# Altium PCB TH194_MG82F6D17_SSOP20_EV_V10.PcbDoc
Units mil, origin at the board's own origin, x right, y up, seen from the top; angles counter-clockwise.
Board outline 2850 x 2110 mil, 2 copper layers (Top Layer, Bottom Layer); 42 components, 34 nets, 215 pads, 149 vias.
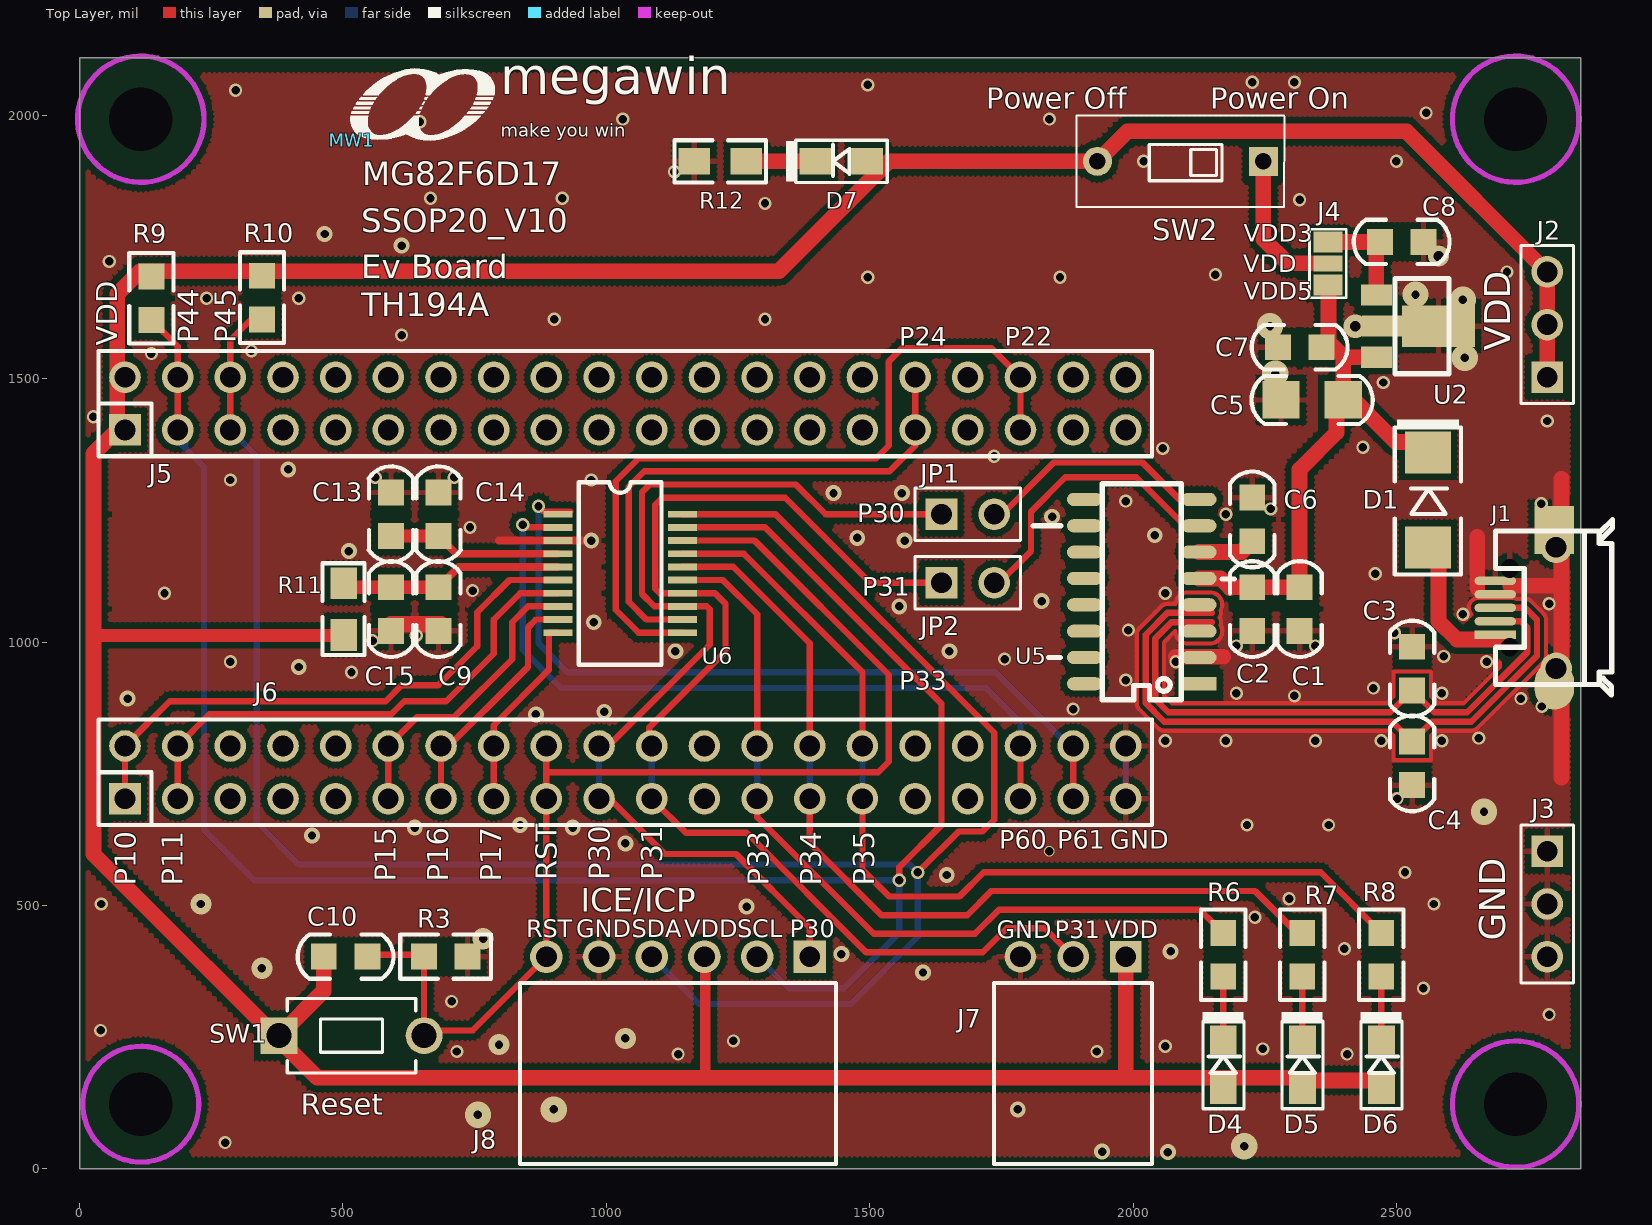
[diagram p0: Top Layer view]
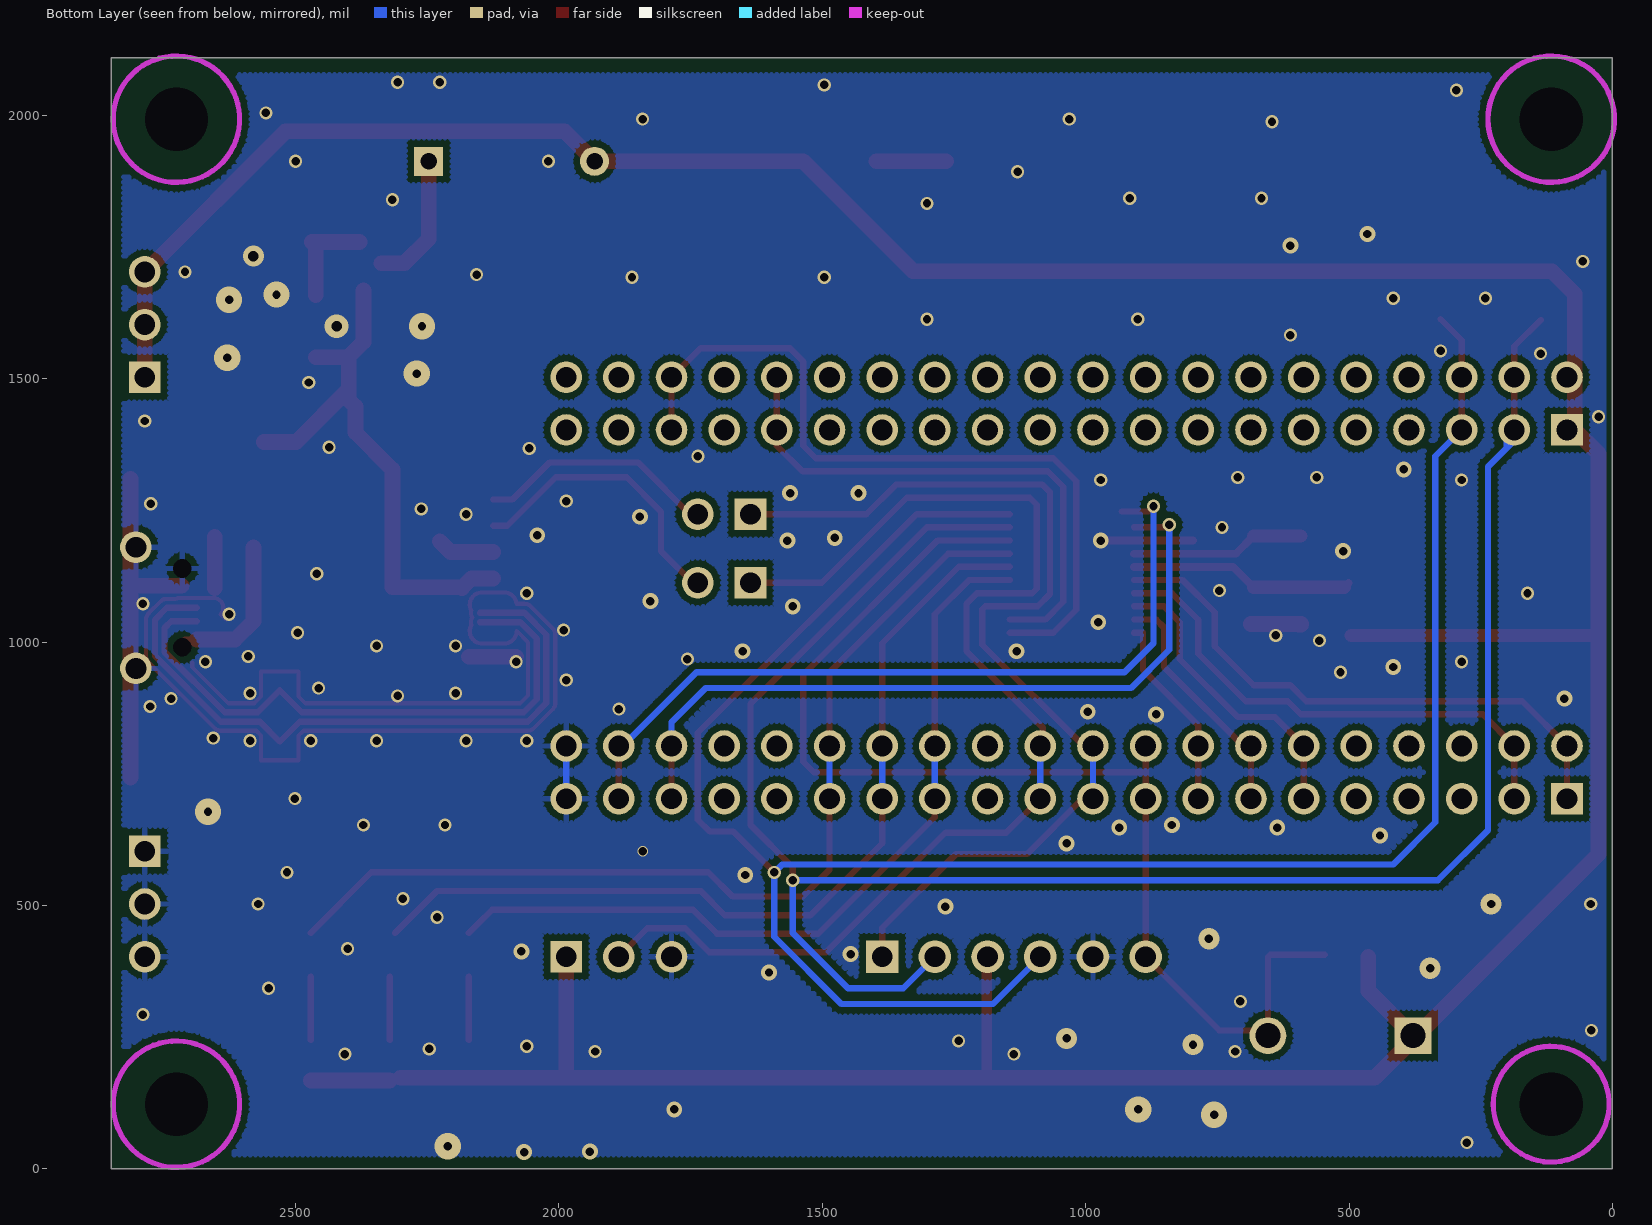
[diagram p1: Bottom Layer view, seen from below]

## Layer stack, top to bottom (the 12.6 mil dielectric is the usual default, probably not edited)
Top Layer: signal copper 1.4
Dielectric: dielectric 12.6, FR-4, Dk 4.8
Bottom Layer: signal copper 1.4

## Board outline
0,0 2850,0 2850,2110 0,2110

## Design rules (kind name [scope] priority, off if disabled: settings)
Clearance 12 [All] p1 off: gap=12
Clearance 7 [All] p2 off: gap=7
Clearance 6 [All] p3: gap=6
ComponentClearance [All] p1 off: gap=10 collisioncheckmode=3 verticalgap=10 showdistances=FALSE
HoleSize [All] p1: absolutevalues=TRUE maxlimit=500 minlimit=1 maxpercent=80.000 minpercent=20.000
MinimumSolderMaskSliver [All] p1 off: minsoldermaskwidth=10
PolygonConnect VIA [ISVIA] p1: connectstyle=Direct reliefconductorwidth=10 reliefentries=4 polygonreliefangle="90 Angle"
PolygonConnect [All] p2: connectstyle=Relief reliefconductorwidth=10 reliefentries=4 polygonreliefangle="90 Angle"
RoutingVias [All] p1: holewidth=16 width=25 viastyle="Through Hole" minholewidth=16 minwidth=24 maxholewidth=28 maxwidth=50
SilkToSilkClearance [All] p1 off: silktosilkclearance=10
SilkscreenOverComponentPads [All] p1 off: minsilkscreentomaskgap=10
SolderMaskExpansion [All] p1 off: expansion=4
Width [All] p1: maxlimit=200 minlimit=6 preferedwidth=10
23 further rules are at their usual default settings.

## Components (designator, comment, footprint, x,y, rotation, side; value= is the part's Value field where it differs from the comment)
C1 "4.7uF" 0805C 2316.34,1063 r270 top
C2 "0.1uF" 0805C 2226.34,1063 r90 top
C3 "15pF" 0805C 2530,950 r90 top
C4 "15pF" 0805C 2530,770 r270 top
C5 "4.7uF" 1206C 2340,1460 r180 top
C6 "1uF" 0805C 2226.34,1233 r270 top
C7 "0.1uF" 0805C 2316.34,1560 r180 top
C8 "4.7uF" 0805C 2510,1760 r0 top
C9 "0.1uF" 0805C 681.34,1063 r90 top
C10 "4.7uF" 0805C 505,403 r0 top
C13 "4.7uF" 0805C 591.34,1243 r90 top
C14 "0.1uF" 0805C 681.34,1243 r270 top
C15 "4.7uF" 0805C 591.34,1063 r270 top
D1 "1N5817" D5817_SMD_1 2560,1270 r270 top
D4 "Green" 0805D#1 2171.34,198 r90 top
D5 "Red" 0805D#1 2321.34,198 r90 top
D6 "Green" 0805D#1 2471.34,198 r90 top
D7 "Yellow" 0805D#2 1446.34,1913 r180 top
J1 "Micro USB母座" JACK_USB_SMD290X220P065 2687.8,1065.28 r180 top
J2 "CON3" PS3P254 2786.34,1503 r90 top
J3 "CON3" PS3P254 2786.34,603 r270 top
J4 "*" JUMP3_SMD 2370,1719 r90 top
J5 "CON40A" PS20X2P254 86.34,1403 r0 top locked
J6 "CON40A" PS20X2P254 86.34,703 r0 top locked
J7 "*" PS3P254f_90 1986.34,403 r180 top
J8 "*" PS6P254F_90 1386.34,403 r180 top locked
JP1 "JUMPER2" PS2P254 1636.34,1243 r0 top
JP2 "JUMPER2" PS2P254 1636.34,1113 r0 top
MW1 "MW-A4" MEGAWIN_3.4 516.34,1953 r0 top
R3 "47K" 0805R#1 695,403 r180 top
R6 "1K" 0805R#1 2171.34,406.66 r270 top
R7 "1K" 0805R#1 2321.34,406.66 r270 top
R8 "1K" 0805R#1 2471.34,406.66 r270 top
R9 "4.7K" 0805R#1 136.34,1653 r90 top
R10 "4.7K" 0805R#1 346.34,1654.34 r90 top
R11 "10" 0805R#2 501.34,1063 r90 top
R12 "1K" 0805R#2 1216.34,1913 r0 top
SW1 "SW TACT-SPST" SW_T_2P 516.34,253 r0 top
SW2 "指撥開關" DIP2_SW 2247.38,1913 r180 top
U2 "AIC1734-33(SOT-89)" SOT89 2461.89,1600 r270 top
U5 "MA111AS16" SO16_150P127 2016.5,1096 r180 top
U6 "MG82F6D17_SSOP-20(150mil)" SSOP20_150P0635 1026.34,1130.5 r270 top

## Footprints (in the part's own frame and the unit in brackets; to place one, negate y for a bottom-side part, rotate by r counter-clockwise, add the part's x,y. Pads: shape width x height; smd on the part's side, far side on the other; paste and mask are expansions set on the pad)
0805C [mm]
  rect 1.25x1.25 smd: 1(-1.05,0) 2(1.05,0)
  silkscreen extent -2.31,-1.07 2.31,1.07
0805D#1 [mm]
  rect 1.4x1.3 smd: 1(-1.192,0) 2(1.192,0)
  silkscreen extent -2.12,-1 2.53,1
0805D#2 [mm]
  rect 1.524x1.27 smd: 1(-1.25,0) 2(1.25,0)
  silkscreen extent -2.21,-1.02 2.67,1.02
0805R#1 [mm]
  rect 1.25x1.25 smd: 1(-1.05,0) 2(1.05,0)
  silkscreen extent -2.18,-1.07 2.18,1.07
0805R#2 [mm]
  rect 1.524x1.27 smd: 1(-1.25,0) 2(1.25,0)
  silkscreen extent -2.21,-1.02 2.21,1.02
1206C [mm]
  rect 1.8x1.8 smd: 1(-1.5,0) 2(1.5,0)
  silkscreen extent -2.92,-1.15 2.92,1.16
D5817_SMD_1 [mil]
  rect 80x86.61 smd: 1(90,0) 2(-90,0)
  silkscreen extent -153,-63 142,63
DIP2_SW [mm]
  rect 1.4x1.4 hole 0.8: 1(0,0)
  round 1.4 hole 0.8: 2(8,0)
  silkscreen extent -1.02,-2.2 9.02,2.2
JACK_USB_SMD290X220P065 [mm]
  rect 1.9x1.8 on Mech2: 0(-2.85,-1.15) 0(-2.85,1.15)
  round 0.8 hole 0.9 unplated: 1(-0.7,1.9) 5(-0.7,-1.9)
  rect 2x0.4 smd: 1(0,1.3)
  oval 2x0.4 smd: 2(0,0.65) 3(0,0) 4(0,-0.65) 5(0,-1.3)
  round 1.524 hole 1: 5(-2.931,2.921) 5(-2.931,-2.921)
  oval 1.9x2.3 smd: 5(-2.85,3.75)
  rect 1.9x2.3 smd: 5(-2.85,-3.75)
  silkscreen extent -5.65,-4.25 -0.01,4.2
JUMP3_SMD [mil]
  rect 40x55 smd: 1(-41,0) 3(41,0)
  rect 30x55 smd: 2(0,0)
  silkscreen extent -65,-35 65,35
MEGAWIN_3.4 [mil]
  silkscreen extent -2,0 272,135
PS2P254 [mil]
  rect 60x60 hole 39.37: 1(0,0)
  round 60 hole 39.37: 2(100,0)
  silkscreen extent -50,-50 150,50
PS3P254 [mil]
  rect 60x60 hole 39.37: 1(0,0)
  round 60 hole 39.37: 2(100,0) 3(200,0)
  silkscreen extent -50,-50 250,50
PS3P254f_90 [mil]
  rect 60x60 hole 39.37: 1(0,0)
  round 60 hole 39.37: 2(100,0) 3(200,0)
  silkscreen extent -50,50 250,394
PS6P254F_90 [mil]
  rect 62x62 hole 39.37: 1(0,0)
  round 62 hole 39.37: 2(100,0) 3(200,0) 4(300,0) 5(400,0) 6(500,0)
  silkscreen extent -50,50 550,394
PS20X2P254 [mil]
  rect 60x60 hole 39.37: 1(0,0)
  round 60 hole 39.37: 2(0,100) 3(100,0) 4(100,100) 5(200,0) 6(200,100) 7(300,0) 8(300,100) 9(400,0) 10(400,100) 11(500,0) 12(500,100) 13(600,0) 14(600,100) 15(700,0) 16(700,100) 17(800,0) 18(800,100) 19(900,0) 20(900,100) 21(1000,0) 22(1000,100) 23(1100,0) 24(1100,100) 25(1200,0) 26(1200,100) 27(1300,0) 28(1300,100) 29(1400,0) 30(1400,100) 31(1500,0) 32(1500,100) 33(1600,0) 34(1600,100) 35(1700,0) 36(1700,100) 37(1800,0) 38(1800,100) 39(1900,0) 40(1900,100)
  silkscreen extent -50,-50 1950,150
SO16_150P127 [mil]
  rect 67x25 smd: 1(-108.5,175)
  oval 67x25 smd: 2(-108.5,125) 3(-108.5,75) 4(-108.5,25) 5(-108.5,-25) 6(-108.5,-75) 7(-108.5,-125) 8(-108.5,-175) 9(108.5,-175) 10(108.5,-125) 11(108.5,-75) 12(108.5,-25) 13(108.5,25) 14(108.5,75) 15(108.5,125) 16(108.5,175)
  silkscreen extent -176,-205 206,205
SOT89 [mm]
  rect 1.016x1.5 smd: 1(-1.5,0) 3(1.5,0)
  rect 2x3.5 smd: 2(0,3)
  rect 1.016x2.6 smd: 2(0,0.6)
  silkscreen extent -2.3,0.9 2.3,3.5
SSOP20_150P0635 [mil]
  rect 13x55.12 smd: 1(-112.5,-118.11) 2(-87.5,-118.11) 3(-62.5,-118.11) 4(-37.5,-118.11) 5(-12.5,-118.11) 7(37.5,-118.11) 8(62.5,-118.11) 9(87.5,-118.11) 10(112.5,-118.11) 11(112.5,118.11) 12(87.5,118.11) 13(62.5,118.11) 14(37.5,118.11) 15(12.5,118.11) 16(-12.5,118.11) 17(-37.5,118.11) 18(-62.5,118.11) 19(-87.5,118.11) 20(-112.5,118.11)
  rect 13x55.12 smd mask+4: 6(12.5,-118.11)
  silkscreen extent -173,-79 173,79
SW_T_2P [mil]
  rect 70x70 hole 47.24: 1(-137.79,0)
  round 70 hole 47.24: 2(137.79,0)
  silkscreen extent -122,-71 122,71

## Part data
C1 C5 C8 C13 C15: library part CAP
C2 C3 C4 C6 C7 C9 C14: library part "CAP NP"
C10: library part C
D1: library part DIODE_ZD, "Schottky Diode"
D4 D5 D6 D7: library part LED
J1: library part CON5, "Connector"
J4 J7: library part CON3
J8: library part CON6
R3 R9 R10 R11: library part R
R6 R7 R8 R12: library part R_Dup1
SW2: library part SW-2
U2: library part AIC1734-33(SOT-89)_0
U6: library part MG82G6D17_SSOP-20

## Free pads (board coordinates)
  round 40 hole 120 unplated: 0(116.34,123) 0(116.34,1993) 0(2726.34,123) 0(2726.34,1993)

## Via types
v1: diameter 25, hole 16, Top Layer to Bottom Layer, tented both sides, 99 vias
v2: diameter 30, hole 16, Top Layer to Bottom Layer, tented both sides, 33 vias
v3: diameter 50, hole 16, Top Layer to Bottom Layer, tented both sides, 9 vias
v4: diameter 40, hole 16, Top Layer to Bottom Layer, tented both sides, 5 vias
v5: diameter 45, hole 20, Top Layer to Bottom Layer, tented both sides, 1 vias
v6: diameter 40, hole 20, Top Layer to Bottom Layer, tented both sides, 1 vias
v7: diameter 20, hole 16, Top Layer to Bottom Layer, tented both sides, 1 vias

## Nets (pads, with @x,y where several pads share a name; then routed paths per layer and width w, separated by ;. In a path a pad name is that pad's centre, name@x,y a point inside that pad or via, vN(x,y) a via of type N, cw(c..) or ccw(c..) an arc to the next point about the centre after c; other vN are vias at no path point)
D+: C4.1 J1.3 U5.4 | length 1271.3
  Top Layer w12: 2150,1056 2065.54,1056 2024,1014.46 2024,884.54 2059.54,849 2492.34,849 C4.1 2567.66,849 2642,849 2767,974 2767,1043 2744.72,1065.28 J1.3
D-: C3.1 J1.2 U5.3 | length 1147.1
  Top Layer w12: 2150,1038 2073,1038 2042,1007 2042,892 2067,867 2488.34,867 C3.1 2571.66,867 2634.54,867 2749,981.46 2749,1027 2736.32,1039.69 J1.2
GND_POWER: C1.2 C2.1 C3.2 C4.2 C5.2 C6.1 C7.2 C8.2 C9.1 C13.2 C14.1 C15.2 J1.4 J1.5 J3.1 J3.2 J3.3 J6.39 J6.40 J7.3 J8.5 R3.1 R12.1 U2.2 U5.2 U6.3 | length 4084.9
  Top Layer w8: 2047.52,836.98 ccw(c2059.54,849) 2059.54,832 ; 2053.52,1068.02 cw(c2065.54,1056) 2065.54,1073 ; 2080.04,1021 2059,999.96 2059,899.04 2074.04,884 2481.3,884 2494.39,897.1 2494.39,944.27 2565.61,944.27 2565.61,897.1 2578.7,884 2627.5,884 2696.4,952.9 2696.4,961.39 ; 2080.5,1021 ccw(c2104,1021) 2104,997.5 2146,997.5 ccw(c2146,1021) 2169.5,1021 ccw(c2146,1021) 2166.23,1032.95 ccw(c2150,1038) 2167,1038 ccw(c2150,1038) 2164.42,1047 ccw(c2150,1056) 2167,1056 ccw(c2150,1056) 2166.6,1059.68 ccw(c2146,1071) 2169.5,1071 ccw(c2146,1071) 2146,1094.5 2104,1094.5 ccw(c2104,1071) 2080.59,1073 2065.54,1073 ; v1@2626.34,1055 2633.62,1055 2633.11,1051.88 2631.65,1043 2633.61,1044.73 2642.42,1052.48 cw(c2656.3,1065.28) 2656.3,1084.15 2719.29,1084.15 cw(c2719.29,1065.28) 2727.49,1082.28 2744.72,1082.28 ; 2756.75,1077.3 ccw(c2744.72,1065.28) 2744.72,1082.28 ; J1.5@2779.02,961.98 ccw(c2767,974) 2784,974 ; 2779.02,1055.02 cw(c2767,1043) 2784,1043 ; 2007,884.54 ccw(c2024,884.54) 2011.98,872.52 ; 2007,884.54 ccw(c2024,884.54) 2012,872.5 ; 2007,884.54 2007,1014.46 ; 2007,1014.46 cw(c2024,1014.46) 2012,1026.5 ; 2007,1014.46 cw(c2024,1014.46) 2011.98,1026.48 ; 2012,872.5 2047.5,837 ccw(c2059.54,849) 2059.54,832 ; 2012,1026.5 2053.5,1068 cw(c2065.54,1056) 2065.54,1073 ; 2059.54,832 2485.3,832 2494.39,822.9 2494.39,775.73 2565.61,775.73 2565.61,822.9 2574.7,832 2642,832 ; 2642,832 ccw(c2642,849) 2654.02,836.98 ; 2642,832 ccw(c2642,849) 2654.04,837 ; 2654.04,837 2779,961.96 ccw(c2767,974) 2784,974 ; 2744.72,1082.28 cw(c2744.72,1065.28) 2756.76,1077.28 2779,1055.04 cw(c2767,1043) 2784,1043 ; 2784,974 2784,1043
  Top Layer w12: U6.3@911.34,1193 v2(971.34,1193) v2@976.34,1193
  Top Layer w15: 796.34,1193 U6.3 v2(971.34,1193)
  Top Layer w30: C15.2@591.34,1033 C15.2@596.34,1033 ; C15.2@591.34,1034.34 681.34,1034.34 C9.1@686.34,1034.34 ; v1@2081.34,972.34 2171.34,972.34 ; 2653.66,1102.91 2653.66,1200 ; 2716.34,1107.32 2813.43,1107.32 ; 2813.66,743 2813.66,1310
  Bottom Layer w12: J6.39 J6.40
  other v1: 276.34,50 1136.34,218 2406.34,218 716.34,223 1931.34,223 2246.34,228 2061.34,233 1241.34,243 40,263 2790,293 706.34,318 2551.34,343 2401.34,418 2231.34,478 41.34,503 2571.34,503 2296.34,513 2516.34,563 2216.34,653 2371.34,653 2501.34,703 2061.34,813 2176.34,813 2346.34,813 2471.34,813 2586.34,813 2656.34,818 1886.34,873 2776.34,878 2736.34,893 2306.34,898 2196.34,903 2586.34,903 2456.34,913 1986.34,928 516.34,943 286.34,963 2081.34,963 2671.34,963 1756.34,968 2590,973 2196.34,993 2346.34,993 556.34,1003 639.34,1013 2496.34,1018 1991.34,1023 2626.34,1053 2790,1073 161.34,1093 2061.34,1093 746.34,1098 2460,1130 741.34,1218 2176.34,1243 2261.34,1253 2775,1263 1986.34,1268 286.34,1308 971.34,1308 561.34,1313 711.34,1313 1736.34,1353 2056.34,1368 2436.34,1370 2786.34,1420 26.34,1428 2475,1493 136.34,1548 326.34,1553 611.34,1583 901.34,1613 1301.34,1613 241.34,1653 416.34,1653 1496.34,1693 1861.34,1693 2156.34,1698 2710,1703 56.34,1723 1301.34,1833 2316.34,1840 666.34,1843 916.34,1843 1129.34,1893 2020,1913 2500,1913 646.34,1988 1031.34,1993 1841.34,1993 2556.34,2005 296.34,2048 1496.34,2058 2226.34,2063 2306.34,2063
  other v2: 2066.34,32 1941.34,33 1781.34,113 1601.34,373 1446.34,408 2071.34,413 1266.34,498 1646.34,558 1036.34,618 441.34,633 636.34,648 936.34,648 836.34,653 866.34,863 996.34,868 91.34,893 416.34,953 1131.34,983 1651.34,983 976.34,1038 1556.34,1068 1826.34,1078 511.34,1173 1566.34,1193 1476.34,1198 2041.34,1203 1846.34,1238 1431.34,1283 1561.34,1283 396.34,1328 611.34,1753 465.34,1775
  other v3: 2211.34,43 756.34,103 900.34,113 2666.34,678 2270,1510 2630,1540 2260,1600 2626.34,1650 2536.34,1660
  other v4: 796.34,236 1036.34,248 346.34,381 766.34,437 230.34,503
  other v5: 2422.33,1600
  other v6: 2580,1733
  other v7: 1841.34,603
MA111_RX: JP2.2 U5.7 | length 550.6
  Top Layer w12: JP2.2@1741.34,1108 1806.34,1173 1806.34,1248 1871.34,1313 2006.34,1313 2098.34,1221 U5.7
MA111_TX: JP1.2 U5.8 | length 454.1
  Top Layer w12: JP1.2@1743.84,1235.5 1849.62,1341.28 2018.05,1341.28 2088.34,1271 U5.8
NetC6_2: C6.2 U5.6 | length 109.9
  Top Layer w30: U5.6 2205.68,1171 C6.2
NetC9_2: C9.2 C15.1 R11.2 U6.5 | length 426.2
  Top Layer w15: R11.2 R11.2@509.21,1104.34 ; C9.2 720,1143 U6.5
  Top Layer w25: R11.2@509.21,1104.34 C15.1 C9.2
NetC13_1: C13.1 C14.2 U6.4 | length 330.8
  Top Layer w15: C14.2 715,1168 U6.4
  Top Layer w25: C13.1 C14.2
NetD1_1: D1.1 J1.1 | length 284.5
  Top Layer w12: 2687.8,1005 J1.1@2710,1005
  Top Layer w30: D1.1@2580,1180 2580,1040 2615,1005 2687.8,1005
NetD4_2: D4.2 R6.2 | length 120.4
  Top Layer w12: D4.2 R6.2
NetD5_2: D5.2 R7.2 | length 120.4
  Top Layer w12: D5.2 R7.2
NetD6_2: D6.2 R8.2 | length 120.4
  Top Layer w12: D6.2 R8.2
NetD7_2: D7.2 R12.2 | length 131.6
  Top Layer w30: R12.2 D7.2
NetJ4_2: J4.2 SW2.1 | length 256.1
  Top Layer w30: SW2.1 2247.38,1765.62 2293.5,1719.5 2337,1719.5
P10: J6.1 J6.2 U6.6 | length 1090.4
  Top Layer w12: J6.1 J6.2 171.34,888 581.34,888 611.34,918 681.34,918 755.34,992 755.34,1057 816.34,1118 U6.6
P11: J6.3 J6.4 U6.7 | length 980.1
  Top Layer w12: J6.3 J6.4 246.34,863 591.69,863 616.69,888 696.34,888 786.34,978 786.34,1043 836.34,1093 U6.7
P15: J6.11 J6.12 U6.8 | length 572.7
  Top Layer w12: J6.11 J6.12 641.34,858 711.34,858 821.34,968 821.34,1038 851.34,1068 U6.8
P16: J6.13 J6.14 U6.9 | length 456.4
  Top Layer w12: J6.13 686.34,788 851.34,953 851.34,1028 866.34,1043 U6.9
P17: J6.15 J6.16 U6.10 | length 375.4
  Top Layer w12: J6.15 J6.16 786.34,842.64 891.34,947.64 891.34,1018 U6.10
P22: J5.35 J5.36 U6.11 | length 1495
  Top Layer w12: U6.11 1061.34,1018 1017.76,1061.58 1017.76,1305.48 1061.69,1349.42 1151.34,1349.42 ; 1168.05,1349.42 1151.34,1349.42 ; J5.35 J5.36 1731.34,1558 1561.34,1558 1536.34,1533 1536.34,1373 1512.76,1349.42 1151.34,1349.42
P24: J5.31 J5.32 U6.12 | length 1147.4
  Top Layer w12: U6.12 1076.34,1043 1042.76,1076.58 1042.76,1295.13 1072.05,1324.42 ; 1168.05,1324.42 1072.05,1324.42 ; 1372.76,1324.42 1361.34,1324.42 ; J5.32 J5.31 1586.34,1373 1537.76,1324.42 1361.34,1324.42 ; 1072.05,1324.42 1361.34,1324.42
P30/RXD: J6.19 J6.20 J8.1 JP1.1 U6.13 | length 2013.8
  Top Layer w12: J6.19 1006.34,703 1111.34,598 1246.34,598 1386.34,458 J8.1 ; J6.20 1003.91,803 1196.34,995.43 1196.34,1062.64 1190.98,1068 U6.13 1091.34,1068 1067.76,1091.58 1067.76,1284.77 1082.4,1299.42 1236.34,1299.42 ; 1304.92,1299.42 1236.34,1299.42 ; JP1.1 1416.34,1243 1359.92,1299.42 1236.34,1299.42
  Bottom Layer w12: J6.19 J6.20
P31/TXD: J6.21 J6.22 J7.2 JP2.1 U6.14 | length 2325.1
  Top Layer w12: J6.22@1081.34,808 1081.34,838 1226.34,983 1226.34,1073 1206.34,1093 U6.14 1101.34,1093 1092.76,1101.58 1092.76,1260.83 1106.34,1274.42 1271.34,1274.42 ; J6.21 1151.34,638 1266.34,638 1493.16,411.17 1714.51,411.17 1760.27,456.93 1832.4,456.93 J7.2 ; 1288.5,1274.42 1271.34,1274.42 ; JP2.1 1501.34,1113 1339.92,1274.42 1271.34,1274.42
  Bottom Layer w12: J6.21 J6.22
P33: J6.25 J6.26 R6.1 U6.15 | length 1628.7
  Top Layer w12: U6.15 1221.34,1118 1286.34,1053 J6.26 ; J6.25 1286.34,668 1507.81,446.53 1699.87,446.53 1745.63,492.29 1801.34,492.29 ; 1821.34,492.29 1801.34,492.29 ; 2142.45,476.89 R6.1 2127.05,492.29 1801.34,492.29
  Bottom Layer w12: J6.25 J6.26
P34: J6.27 J6.28 R7.1 U6.16 | length 1866.8
  Top Layer w12: U6.16 1241.34,1143 ; 1311.34,1073 1241.34,1143 ; J6.27 1386.34,618 1522.45,481.89 1685.22,481.89 1730.98,527.64 1796.34,527.64 ; J6.28 1386.34,998 1241.34,1143 ; 1821.34,527.64 1796.34,527.64 ; 2248.16,511.18 2267.66,491.68 ; R7.1@2311.34,448 2267.66,491.68 ; 1796.34,527.64 2231.69,527.64 2267.66,491.68
  Bottom Layer w12: J6.27 J6.28
P35: J6.29 J6.30 R8.1 U6.17 | length 1998.8
  Top Layer w12: U6.17 1261.34,1168 ; 1336.34,1093 1261.34,1168 ; J6.29 1486.34,568 1537.1,517.24 1670.58,517.24 1716.34,563 1811.34,563 ; J6.30 1486.34,943 1261.34,1168 ; 1821.34,563 1811.34,563 ; R8.1 2356.34,563 1811.34,563
  Bottom Layer w12: J6.29 J6.30
P44: J5.3 J5.4 J8.2 R9.1 U6.19 | length 3941.2
  Top Layer w12: R9.1 186.34,1561.66 J5.4 J5.3 ; U6.19 1301.34,1218 1636.34,883 1636.34,653 1556.34,573 v1(1556.34,548)
  Bottom Layer w12: J5.3@186.34,1383 236.34,1333 236.34,643 ; 201.34,1373 J5.3@201.34,1393 ; 281.34,598 236.34,643 ; 971.34,548 1021.34,548 ; J8.2 1346.34,343 1451.34,343 1556.34,448 v1(1556.34,548) 1021.34,548 ; J8.2@1288.34,405 J8.2@1288.34,426 ; 236.34,643 331.34,548 1021.34,548
P45: J5.5 J5.6 J8.4 R10.1 U6.20 | length 4801.1
  Top Layer w12: J5.5 J5.6 286.34,1573 R10.1@326.34,1613 ; 1276.34,1243 U6.20 1321.34,1243 1736.34,828 1736.34,663 1713.89,640.55 1668.89,640.55 v1(1591.34,563)
  Bottom Layer w12: J5.5 336.34,1353 336.34,658 416.34,578 1516.34,578 ; 1001.34,578 1516.34,578 ; J8.4@1077.84,415.5 1088.34,426 J8.4@1088.34,406 ; J8.4 1176.34,313 1463.77,313 1591.34,440.57 v1(1591.34,563) 1576.34,578 1516.34,578
P60: J6.35 J6.36 U6.2 | length 1446.3
  Top Layer w12: v1@841.34,1218 U6.2 ; J6.35 J6.36
  Bottom Layer w12: v1@841.34,1218 841.34,985.57 913.91,913 1721.34,913 1786.34,848 J6.36
  other v1: 841.34,1223
P61: J6.37 J6.38 U6.1 | length 1512.4
  Top Layer w12: v1(871.34,1258) 881.34,1248 U6.1@931.34,1248 ; J6.37 J6.38
  Bottom Layer w12: v1(871.34,1258) 871.34,998 926.34,943 1738.87,943 J6.38@1878.87,803
RST: C10.2 J6.17 J6.18 J8.6 R3.2 SW1.2 U6.18 | length 2271
  Top Layer w12: C10.2@546.34,406.81 R3.2@649.85,406.81 ; R3.2@654.13,402.53 654.13,263 746.34,263 J8.6 ; J8.6@886.34,407 J6.17 886.34,753 ; J6.18 886.34,753 ; J8.6@888.34,405 J8.6@888.34,426 ; U6.18 1281.34,1193 1536.34,938 1536.34,773 1516.34,753 886.34,753
VDD: C10.1 D4.1 D5.1 D6.1 D7.1 J2.1 J2.2 J2.3 J5.1 J5.2 J7.1 J8.3 R9.2 R10.2 R11.1 SW1.1 SW2.2 | length 7958.3
  Top Layer w20: 1188.34,180 J8.3@1188.34,403
  Top Layer w25: 26.34,1013 R11.1@496.34,1013
  Top Layer w30: SW1.1 463.66,338.12 C10.1 ; SW1.1@382.74,249.56 SW1.1@382.82,252.9 ; J7.1@1986.34,413 J7.1 1986.34,173 ; D5.1@2301.34,173 1986.34,173 ; D5.1@2321.34,168 D6.1@2471.34,168 ; J2.1 J2.2 J2.3@2786.34,1702.66 ; 1986.34,173 451.34,173 26.34,598 26.34,1013 26.34,1357.91 71.43,1403 71.43,1660.97 114.79,1704.34 1327.68,1704.34 1536.34,1913 SW2.2 1989.42,1970 2519,1970 J2.3@2786,1703 ; J2.3@2786,1703 J2.3 J2.3@2786.34,1702.66 ; J2.3@2786,1703 J2.3@2786.34,1702.66
VDD3: C8.1 J4.3 U2.1 | length 183.8
  Top Layer w30: J4.3@2379,1760 C8.1 ; U2.1 C8.1@2461.89,1753.23
VDD5: C1.1 C2.2 C5.1 C7.1 D1.2 J4.1 U2.3 U5.5 | length 1071.5
  Top Layer w30: U5.5 2166.34,1121 2184.34,1103 2185.68,1104.34 C2.2 C1.1 2316.34,1328 2386.34,1398 2386.34,1447.28 C5.1 C5.1@2399.06,1480 ; J4.1@2371.34,1667.66 2371.34,1570 2400.39,1540.94 U2.3 ; 2399.06,1539.61 C5.1@2399.06,1480 ; D1.2@2560,1380 2499.06,1380 C5.1@2399.06,1480
pads on no net: J1.0 J5.7 J5.8 J5.9 J5.10 J5.11 J5.12 J5.13 J5.14 J5.15 J5.16 J5.17 J5.18 J5.19 J5.20 J5.21 J5.22 J5.23 J5.24 J5.25 J5.26 J5.27 J5.28 J5.29 J5.30 J5.33 J5.34 J5.37 J5.38 J5.39 J5.40 J6.5 J6.6 J6.7 J6.8 J6.9 J6.10 J6.23 J6.24 J6.31 J6.32 J6.33 J6.34 U5.1 U5.9 U5.10 U5.11 U5.12 U5.13 U5.14 U5.15 U5.16

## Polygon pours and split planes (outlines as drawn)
GND_POWER on Bottom Layer "Bottom Layer-No Net" (hatched 90Degree grid 10 track 10, remove dead copper, pour order 1001): 16.34,27 2826.34,27 2826.34,2078 16.34,2078
GND_POWER on Top Layer "Bottom Layer-No Net" (hatched 90Degree grid 10 track 10, remove dead copper, pour order 1001): 16.34,27 2826.34,27 2826.34,2078 16.34,2078

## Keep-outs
Keep-Out Layer:
  circle w10: c2726.34,123 r120
  circle w10: c116.34,1993 r120
  circle w10: c116.34,123 r110
  circle w10: c2726.34,1993 r120

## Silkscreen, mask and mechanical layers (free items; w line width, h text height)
Top Overlay:
  text "Power Off" at 1721.34,2013 h40
  text "Power On" at 2146.34,2013 h40
  text "MG82F6D17" at 536.34,1868 h45
  text "SSOP20_V10" at 534.91,1778.43 h45
  text "VDD3" at 2210,1760 h33
  text "VDD" at 2209.58,1702 h33
  text "Ev Board" at 534.91,1690.93 h45
  text "VDD5" at 2210,1650 h33
  text "TH194A" at 534.91,1618.43 h45
  text "P44" at 226.34,1568 h40 r90
  text "P45" at 296.34,1568 h40 r90
  text "VDD" at 71.34,1563 h40 r90
  text "P24" at 1556.34,1563 h35
  text "P22" at 1756.34,1563 h35
  text "VDD" at 2716.34,1553 h50 r90
  text "P30" at 1476.34,1228 h35
  text "P31" at 1486.34,1088 h35
  text "P33" at 1556.34,910 h35
  text "P60" at 1746.34,608 h35
  text "P61" at 1856.34,608 h35.43
  text "GND" at 1956.34,608 h35.43
  text "RST" at 906.34,548 h40 r90
  text "P30" at 1006.34,548 h40 r90
  text "P31" at 1106.34,548 h40 r90
  text "P15" at 600.29,544.95 h40 r90
  text "P16" at 700.29,544.95 h40 r90
  text "P17" at 800.29,544.95 h40 r90
  text "P10" at 106.34,538 h40 r90
  text "P11" at 196.34,538 h40 r90
  text "P33" at 1308.34,538 h40 r90
  text "P34" at 1408.34,538 h40 r90
  text "P35" at 1508.34,538 h40 r90
  text "ICE/ICP" at 951.34,488 h45
  text "RST" at 848.34,440 h33
  text "GND" at 943.34,440 h33
  text "SDA" at 1048.34,440 h33
  text "VDD" at 1148.34,440 h33
  text "SCL" at 1248.34,440 h33
  text "P30" at 1348.34,440 h33
  text "GND" at 1741.34,438 h33
  text "P31" at 1851.34,438 h33
  text "VDD" at 1946.34,438 h33
  text "GND" at 2706.34,433 h50 r90
  text "Reset" at 420,103 h40
Mechanical 1:
  the board outline again, w13
Mechanical 2:
  lines w6: -53.66,303 86.34,303 ; 386.34,2003 386.34,2143 ; 1286.34,2003 1286.34,2143 ; 1486.34,2003 1486.34,2143 ; 2386.34,2003 2386.34,2143 ; 2786.34,603 2926.34,603 ; 2786.34,1503 2926.34,1503

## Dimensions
0,0 to 2850,0 on Top Overlay
0,2110 to 0,0 on Top Overlay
